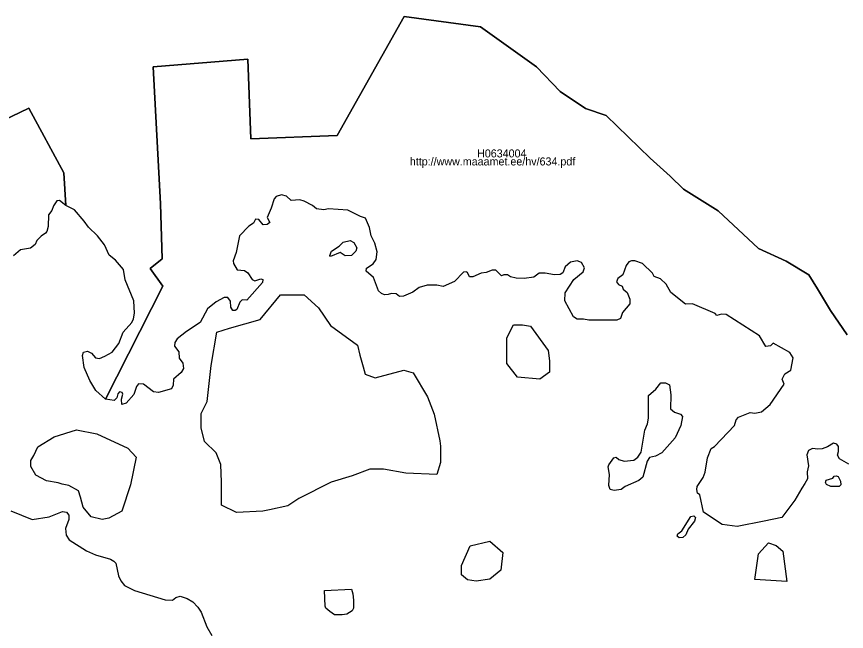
# Model space of a CAD drawing. Extents: x 369010 to 739155, y 6377141 to 6634081.
# Drawn here: x 454636 to 457228, y 6478740 to 6480660 of the extents above; entities that cross this region are included whole.
import ezdxf

# ---------------------------------------------------------------- set-up
doc = ezdxf.new("R2010")
doc.units = 0
for name, color, linetype in [('H_LINK', 7, 'Continuous'), ('H_PIIR', 7, 'Continuous'), ('H_TUNNUS', 7, 'Continuous')]:
    doc.layers.add(name, color=color, linetype=linetype)

msp = doc.modelspace()

# ---------------------------------------------------------------- linework, layer by layer
at = {"layer": 'H_PIIR'}
for points in [[(457229.78, 6479665.6701), (457177.56, 6479742.5), (457137.62, 6479810.1), (457109.98, 6479853.1299), (457039.3301, 6479896.15), (456953.3201, 6479936.1), (456827.3799, 6480052.8701), (456719.1201, 6480120.9401), (456677.0201, 6480161.65), (456615.29, 6480217.7999), (456477.7899, 6480351.1601), (456413.2401, 6480372.21), (456333.27, 6480425.5501), (456259.57, 6480502.54), (456085.4099, 6480627.23), (455846.92, 6480659.55), (455637.2401, 6480288.0799), (455367.48, 6480277.9301), (455358.27, 6480526.28), (455062.77, 6480502.46), (455085.88, 6480074.7701), (455091.18, 6479903.52), (455053.3001, 6479872.64), (455092.5801, 6479817.8899), (454913.7251, 6479465.4995), (454913.5899, 6479465.5247), (454883.91, 6479491.9546), (454865.1399, 6479522.9846), (454847.52, 6479564.3647), (454841.77, 6479601.9146), (454844.83, 6479611.8746), (454857.0899, 6479615.3246), (454869.7299, 6479608.8047), (454882.9499, 6479593.8646), (454895.2101, 6479592.3346), (454912.06, 6479599.2346), (454934.66, 6479611.8746), (454955.35, 6479639.0746), (454969.33, 6479674.3146), (454996.1499, 6479704.9647), (455001.13, 6479716.4647), (455004.57, 6479733.7046), (455001.8899, 6479772.3946), (454975.66, 6479837.9046), (454969.92, 6479869.7046), (454944.63, 6479898.8247), (454925.6799, 6479914.9146), (454910.36, 6479947.4847), (454888.53, 6479975.4546), (454860.5599, 6480002.2747), (454847.54, 6480021.4246), (454817.07, 6480056.6746), (454789.8797, 6480070.0849), (454783.2099, 6480171.95), (454673.77, 6480374.0899), (454224.7199, 6480158.3399)], [(457235.16, 6479262.0846), (457206.12, 6479279.1247), (457199.93, 6479290.7347), (457203.41, 6479302.3547), (457202.6401, 6479317.8347), (457197.61, 6479325.1946), (457187.16, 6479327.9046), (457168.9599, 6479316.6747), (457152.3199, 6479310.4847), (457138.3999, 6479309.3147), (457122.14, 6479310.8647), (457109.37, 6479305.0646), (457103.9501, 6479291.8947), (457109.37, 6479257.4446), (457105.4999, 6479238.8547), (457105.88, 6479216.0146), (457097.37, 6479202.0746), (457088.4027, 6479187.7064), (457066.1777, 6479149.6063), (457025.6963, 6479095.6312), (456970.9275, 6479084.5187), (456886.7898, 6479067.8499), (456839.1647, 6479074.1999), (456781.2208, 6479112.3), (456770.2799, 6479166.4646), (456762.9301, 6479171.8847), (456760.21, 6479182.7246), (456761.38, 6479192.7847), (456780.34, 6479221.0547), (456786.5401, 6479236.9246), (456794.0801, 6479282.2247), (456805.3, 6479310.8747), (456815.75, 6479317.8347), (456878.66, 6479382.8746), (456882.9101, 6479400.6846), (456890.2699, 6479409.2046), (456927.04, 6479423.1446), (456941.36, 6479421.2047), (456962.1962, 6479425.8319), (456989.9775, 6479448.8507), (457033.4801, 6479512.1846), (457026.5199, 6479527.2847), (457035.03, 6479544.3246), (457054.39, 6479555.9346), (457061.35, 6479594.2647), (457051.2899, 6479610.5247), (456998.64, 6479639.9547), (456990.9001, 6479632.2146), (456975.8001, 6479629.8846), (456956.0599, 6479663.1846), (456852.52, 6479729.7747), (456837.8099, 6479730.5447), (456822.71, 6479726.2847), (456817.29, 6479732.4846), (456746.6399, 6479763.0646), (456725.3499, 6479762.2847), (456678.9, 6479798.6846), (456664.97, 6479823.8447), (456647.16, 6479840.4946), (456627.61, 6479847.8546), (456622.5699, 6479858.6946), (456591.22, 6479888.8946), (456566.45, 6479897.0246), (456556.77, 6479897.0246), (456548.2501, 6479893.5346), (456539.74, 6479882.3146), (456529.2901, 6479853.6646), (456513.6201, 6479841.6647), (456510.1299, 6479831.9847), (456515.55, 6479822.6947), (456527.5501, 6479818.4346), (456530.2599, 6479808.7546), (456543.42, 6479797.9147), (456551.55, 6479777.0046), (456551.55, 6479762.6847), (456528.7101, 6479735.5847), (456521.94, 6479716.9946), (456510.7199, 6479712.3546), (456422.85, 6479711.5746), (456406.7899, 6479715.0546), (456387.04, 6479715.0546), (456375.43, 6479722.4147), (456347.9499, 6479771.9747), (456349.6899, 6479796.7547), (456376.7799, 6479838.9547), (456405.43, 6479862.9546), (456409.6899, 6479875.7347), (456400.78, 6479891.9947), (456386.85, 6479897.4146), (456366.33, 6479892.7646), (456349.6899, 6479878.4446), (456341.95, 6479859.4646), (456333.25, 6479854.4347), (456315.8301, 6479852.8846), (456287.18, 6479858.3046), (456268.21, 6479858.6946), (456251.5699, 6479846.3047), (456220.9899, 6479842.4347), (456196.2199, 6479843.2046), (456178.8, 6479847.4647), (456169.31, 6479853.2747), (456158.0899, 6479853.6646), (456150.7301, 6479850.5647), (456132.9301, 6479867.6046), (456120.93, 6479868.3747), (456102.7299, 6479860.6346), (456086.91, 6479858.9947), (456061.2499, 6479846.7346), (456050.52, 6479847.5047), (456043.82, 6479860.9147), (456040.5601, 6479863.2047), (456031.9401, 6479861.2947), (456003.98, 6479832.1746), (455968.3499, 6479816.4747), (455948.8201, 6479820.6846), (455917.98, 6479821.0647), (455893.09, 6479813.4047), (455873.55, 6479799.2246), (455844.8199, 6479786.9647), (455831.8, 6479786.2046), (455821.07, 6479794.2446), (455807.2799, 6479795.0147), (455796.17, 6479791.9446), (455784.68, 6479791.1846), (455775.87, 6479794.6246), (455766.4801, 6479803.0647), (455750.7799, 6479845.2047), (455727.41, 6479865.1246), (455728.56, 6479874.7047), (455749.6299, 6479888.1146), (455758.8199, 6479900.7547), (455762.2699, 6479925.6646), (455754.9901, 6479952.0947), (455743.3099, 6479974.7046), (455738.7099, 6480001.5147), (455726.0701, 6480029.8747), (455710.5601, 6480035.2346), (455670.33, 6480055.5446), (455610.5799, 6480058.9846), (455595.82, 6480056.3047), (455572.4599, 6480058.9846), (455560.58, 6480069.3346), (455534.15, 6480083.5047), (455520.7401, 6480087.7246), (455493.5401, 6480085.4246), (455479.1901, 6480098.8346), (455463.4799, 6480103.0447), (455447.01, 6480098.4447), (455440.5001, 6480090.7846), (455431.3001, 6480061.6647), (455418.28, 6480032.5546), (455427.47, 6480016.4646), (455419.0499, 6480010.3347), (455406.4001, 6480009.5647), (455393, 6480026.4247), (455382.2701, 6480026.8046), (455375.7599, 6480014.9247), (455361.59, 6480005.7347), (455332.28, 6479975.0847), (455321.5499, 6479922.5947), (455312.74, 6479896.9246), (455313.5101, 6479888.4947), (455324.9999, 6479869.3346), (455347.8, 6479867.4146), (455357.75, 6479859.7547), (455371.55, 6479838.6846), (455380.3599, 6479834.4746), (455398.3601, 6479841.3646), (455405.2501, 6479838.3047), (455404.49, 6479829.8746), (455354.69, 6479774.3247), (455340.1301, 6479775.4647), (455332.86, 6479767.8046), (455323.66, 6479745.5846), (455318.87, 6479741.7546), (455311.59, 6479742.1346), (455304.7, 6479752.8647), (455304.3201, 6479771.6346), (455296.2701, 6479783.1346), (455284.4, 6479782.3647), (455259.11, 6479768.5747), (455232.3, 6479746.7346), (455209.9, 6479704.9747), (455166.61, 6479676.6246), (455137.88, 6479653.6347), (455130.22, 6479642.5246), (455129.4601, 6479631.0346), (455142.86, 6479613.4047), (455144.01, 6479593.4846), (455155.12, 6479577.7746), (455157.42, 6479560.9147), (455150.3301, 6479548.2746), (455125.82, 6479527.5846), (455125.05, 6479508.4346), (455119.6901, 6479497.7046), (455079.65, 6479485.8247), (455063.1701, 6479488.1247), (455032.5301, 6479511.8847), (455017.21, 6479513.0247), (455010.31, 6479504.6046), (455002.65, 6479480.0847), (454978.14, 6479452.4946), (454964.73, 6479448.6646), (454963.9601, 6479464.7546), (454968.18, 6479480.8446), (454966.2601, 6479485.8247), (454957.64, 6479487.7446), (454952.66, 6479482.3747), (454949.6, 6479468.9747), (454940.41, 6479460.5446), (454913.7251, 6479465.4995), (455092.5801, 6479817.8899), (455053.3001, 6479872.64), (455091.18, 6479903.52), (455085.88, 6480074.7701), (455062.77, 6480502.46), (455358.27, 6480526.28), (455367.48, 6480277.9301), (455637.2401, 6480288.0799), (455846.92, 6480659.55), (456085.4099, 6480627.23), (456259.57, 6480502.54), (456333.27, 6480425.5501), (456413.2401, 6480372.21), (456477.7899, 6480351.1601), (456615.29, 6480217.7999), (456677.0201, 6480161.65), (456719.1201, 6480120.9401), (456827.3799, 6480052.8701), (456953.3201, 6479936.1), (457039.3301, 6479896.15), (457109.98, 6479853.1299), (457137.62, 6479810.1), (457177.56, 6479742.5), (457229.78, 6479665.6701)], [(454224.7199, 6480158.3399), (454673.77, 6480374.0899), (454783.2099, 6480171.95), (454789.8797, 6480070.0849), (454769.57, 6480085.4047), (454761.9101, 6480084.6347), (454751.19, 6480068.9346), (454745.8201, 6480054.3746), (454735.4801, 6480040.5846), (454735.1, 6480003.8047), (454730.89, 6479988.8547), (454726.6699, 6479983.1147), (454712.3101, 6479974.3046), (454699.6701, 6479960.8946), (454693.9201, 6479947.8647), (454679.3699, 6479936.7546), (454648.7199, 6479931.0046), (454626.51, 6479912.2347)], [(454618.47, 6479116.8846), (454684.74, 6479089.6746), (454737.5999, 6479098.1047), (454778.97, 6479114.5846), (454792.0001, 6479112.2846), (454799.66, 6479103.0846), (454798.8701, 6479089.6746), (454788.5301, 6479061.3246), (454790.45, 6479040.2547), (454800.41, 6479026.0746), (454854.04, 6478991.5946), (454882.0001, 6478979.7147), (454929.3001, 6478965.9247), (454940.03, 6478959.0347), (454945.78, 6478953.2847), (454954.2, 6478914.2046), (454961.1, 6478898.1146), (454972.9699, 6478883.1746), (455004.39, 6478867.4646), (455100.15, 6478838.7246), (455122.75, 6478837.9547), (455133.09, 6478846.0047), (455147.2699, 6478850.2146), (455168.34, 6478843.3246), (455186.34, 6478832.5947), (455202.43, 6478815.7346), (455212.97, 6478800.4147), (455230.59, 6478754.8147), (455245.9099, 6478727.6147)]]:
    msp.add_lwpolyline(points, dxfattribs=at)
for points in [[(455677.3677, 6479960.8426), (455688.9529, 6479954.7189), (455698.8832, 6479937.5066), (455695.4075, 6479927.5763), (455682.3328, 6479914.1705), (455662.4724, 6479912.6809), (455646.7495, 6479923.4387), (455616.1312, 6479910.3639), (455614.1451, 6479914.1705), (455619.6067, 6479927.2454), (455643.7704, 6479942.4717), (455656.3487, 6479955.5464)], [(455244.0548, 6479570.3829), (455260.9881, 6479674.0998), (455301.2049, 6479686.7998), (455396.4551, 6479714.3165), (455459.9552, 6479790.5167), (455534.0387, 6479790.5167), (455578.4888, 6479750.2999), (455616.5888, 6479695.2665), (455701.2557, 6479633.883), (455707.6057, 6479602.1329), (455718.189, 6479566.1495), (455724.539, 6479542.8662), (455756.2891, 6479532.2828), (455845.1893, 6479555.5662), (455874.8227, 6479547.0995), (455919.2728, 6479473.016), (455940.4395, 6479417.9826), (455957.3728, 6479335.4324), (455959.4895, 6479318.499), (455959.4895, 6479267.6989), (455948.9062, 6479229.5989), (455851.5393, 6479233.8322), (455781.6892, 6479246.5322), (455756.2891, 6479246.5322), (455739.3557, 6479246.5322), (455684.3223, 6479225.3655), (455618.7055, 6479206.3155), (455517.1053, 6479155.5154), (455483.2386, 6479132.232), (455426.0885, 6479119.532), (455404.9217, 6479115.2986), (455322.3716, 6479111.0653), (455275.8048, 6479134.3487), (455275.8048, 6479206.3155), (455273.6881, 6479261.3489), (455258.8715, 6479297.3323), (455222.888, 6479333.3157), (455212.3047, 6479375.6492), (455212.3047, 6479420.0992), (455231.3547, 6479458.1993)], [(456166.9233, 6479657.1664), (456188.09, 6479697.3831), (456215.6067, 6479697.3831), (456241.0067, 6479693.1498), (456296.0402, 6479616.9496), (456300.2735, 6479585.1996), (456300.2735, 6479549.2162), (456270.6401, 6479528.0495), (456200.79, 6479534.3995), (456166.9233, 6479576.7329)], [(456648.3796, 6479516.1334), (456663.1096, 6479516.1334), (456675.5222, 6479509.8442), (456678.9979, 6479479.226), (456678.1704, 6479435.2019), (456690.5831, 6479424.7752), (456709.1196, 6479418.486), (456715.2433, 6479410.7073), (456710.4437, 6479382.5716), (456692.7347, 6479345.0023), (456650.8622, 6479297.337), (456631.8292, 6479287.2413), (456612.4652, 6479283.4348), (456605.3485, 6479271.3529), (456591.4463, 6479221.8672), (456579.861, 6479211.7716), (456536.4989, 6479192.0766), (456524.4172, 6479182.8083), (456502.0741, 6479179.6638), (456490.3233, 6479183.4704), (456485.3582, 6479195.5521), (456487.6753, 6479229.977), (456483.5377, 6479253.975), (456486.0202, 6479260.5953), (456501.0811, 6479281.7796), (456508.3632, 6479284.5933), (456516.9694, 6479276.8145), (456533.1889, 6479272.1804), (456563.3106, 6479274.4975), (456576.5509, 6479284.5933), (456586.6465, 6479299.6541), (456597.7355, 6479368.5037), (456606.8381, 6479388.6953), (456609.1552, 6479406.0732), (456609.6517, 6479476.9089), (456632.6568, 6479496.7693)], [(454752.9871, 6479348.1324), (454822.8372, 6479369.2991), (454886.3374, 6479356.5991), (454983.7042, 6479312.149), (455009.1043, 6479284.6323), (454992.1709, 6479197.8488), (454964.6542, 6479115.2986), (454924.4374, 6479094.1319), (454903.2707, 6479089.8986), (454869.404, 6479098.3653), (454844.004, 6479127.9987), (454835.5373, 6479159.7487), (454829.1873, 6479178.7988), (454799.5539, 6479195.7321), (454778.3872, 6479199.9655), (454765.6871, 6479204.1988), (454729.7037, 6479210.5488), (454695.837, 6479227.4822), (454681.0203, 6479254.9989), (454681.0203, 6479274.049), (454689.487, 6479288.8656), (454702.187, 6479316.3824)], [(457204.9695, 6479192.4075), (457178.9854, 6479192.0766), (457165.9107, 6479199.0276), (457162.435, 6479205.1513), (457164.2555, 6479212.1025), (457185.6057, 6479218.3917), (457189.4121, 6479224.8463), (457195.7013, 6479226.0049), (457201.825, 6479223.3567), (457208.7762, 6479208.9579), (457209.9346, 6479197.8692)], [(456750.6611, 6479100.7184), (456756.1228, 6479095.5877), (456753.4746, 6479084.3334), (456733.7796, 6479059.1768), (456726.0009, 6479041.4678), (456716.7328, 6479032.8618), (456704.982, 6479032.5306), (456699.1893, 6479037.9923), (456700.8443, 6479045.2744), (456713.5883, 6479054.2118), (456741.8893, 6479098.7322)], [(456052.623, 6479007.3484), (456114.0065, 6479022.1651), (456154.2232, 6478986.1817), (456147.8732, 6478931.1483), (456114.0065, 6478903.6315), (456071.6731, 6478897.2815), (456044.1564, 6478901.5149), (456025.1063, 6478916.3316), (456025.1063, 6478945.965)], [(456952.7373, 6478982.4775), (456984.4874, 6479016.3443), (457007.7708, 6479007.8776), (457028.9375, 6478990.9442), (457041.6375, 6478895.694), (456942.154, 6478902.044)], [(455597.5388, 6478867.6481), (455682.2056, 6478871.8815), (455686.439, 6478857.0648), (455688.5556, 6478838.0147), (455688.5556, 6478812.6147), (455684.3223, 6478804.148), (455667.3889, 6478793.5647), (455652.5722, 6478791.448), (455629.2889, 6478791.448), (455614.4722, 6478802.0313), (455601.7721, 6478812.6147), (455599.6555, 6478818.9647)]]:
    msp.add_lwpolyline(points, close=True, dxfattribs=at)

# ---------------------------------------------------------------- texts
at = {"layer": 'H_LINK'}
msp.add_text('http://www.maaamet.ee/hv/634.pdf', height=25, dxfattribs=at).set_placement((455864.2385, 6480194.9213))
at = {"layer": 'H_TUNNUS'}
msp.add_text('H0634004', height=25, dxfattribs=at).set_placement((456074.2177, 6480219.9213))

doc.saveas('drawing.dxf')
